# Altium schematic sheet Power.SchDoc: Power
size A4; Date: Not used; ApprovedBy: Not used; CheckedBy: Not used; Author: Not used; CompanyName: STMicroelectronics; DrawnBy: Not used; Engineer: Not used; Organization: Not used; Address1: Not used; Address2: Not used; Address3: Not used; Address4: Not used; DocumentNumber: Not used; Revision: Not used; SheetNumber: 5; SheetTotal: 7
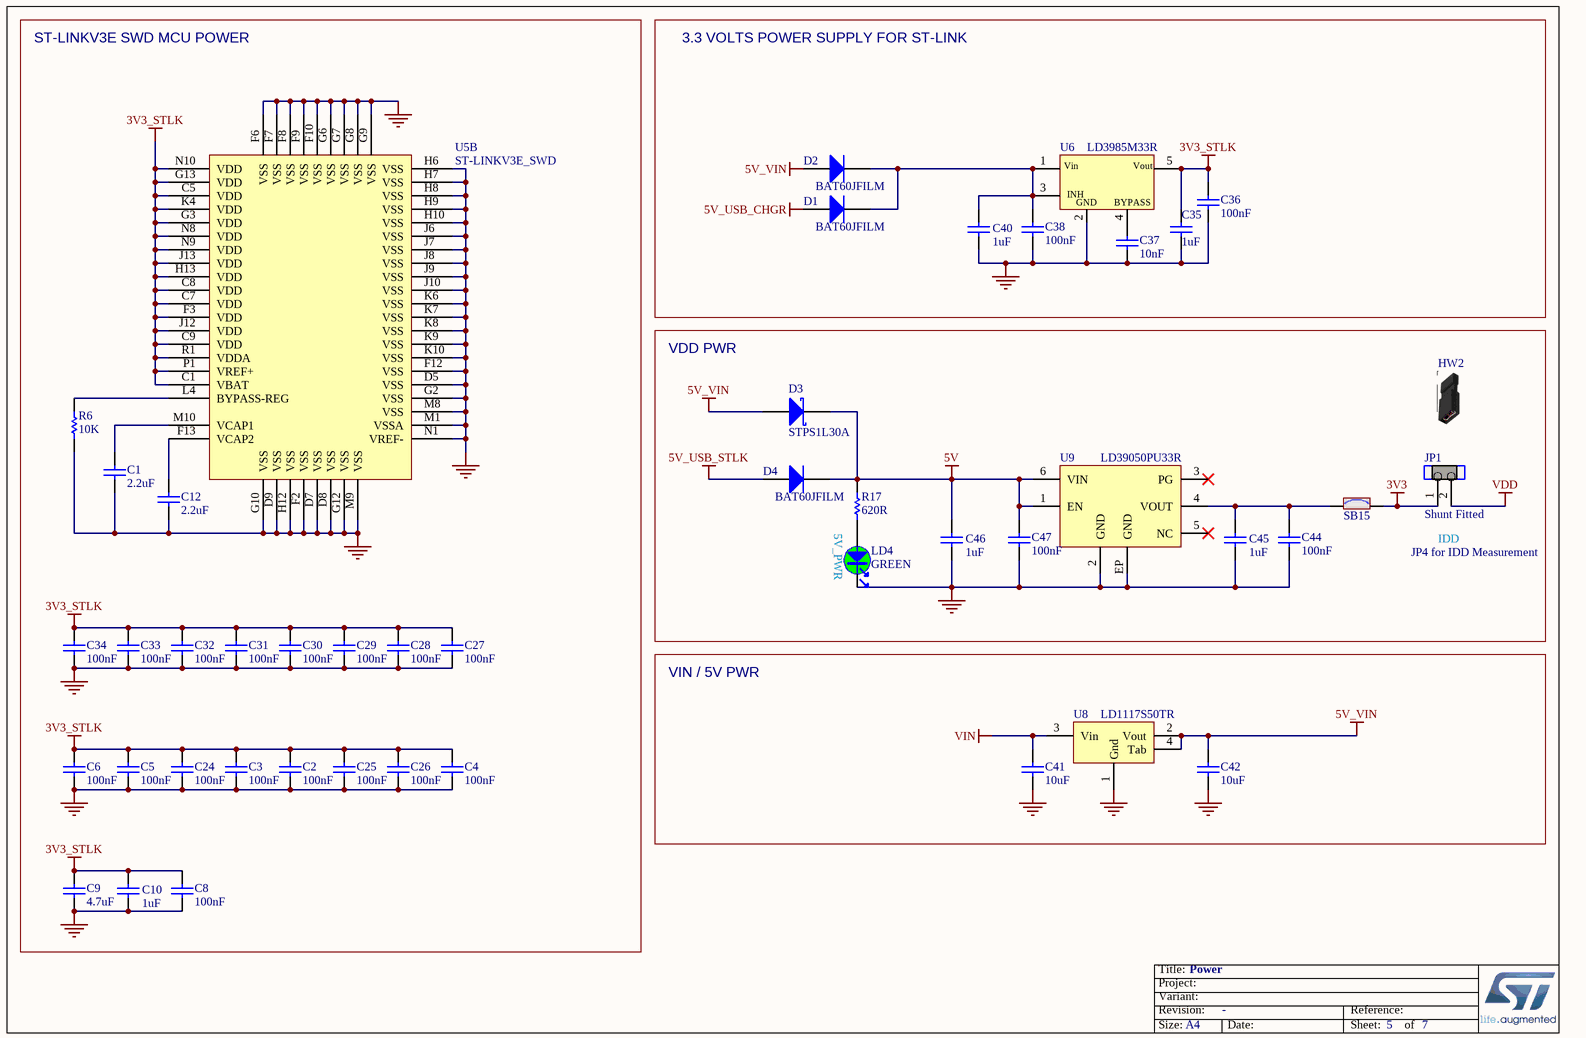
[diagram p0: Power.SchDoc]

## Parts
C1  value 2.2uF  [C0603]
C2  value 100nF  [C0402]
C3  value 100nF  [C0402]
C4  value 100nF  [C0402]
C5  value 100nF  [C0402]
C6  value 100nF  [C0402]
C8  value 100nF  [C0402]
C9  value 4.7uF  [C0603]
C10  value 1uF  [C0603]
C12  value 2.2uF  [C0603]
C24  value 100nF  [C0402]
C25  value 100nF  [C0402]
C26  value 100nF  [C0402]
C27  value 100nF  [C0402]
C28  value 100nF  [C0402]
C29  value 100nF  [C0402]
C30  value 100nF  [C0402]
C31  value 100nF  [C0402]
C32  value 100nF  [C0402]
C33  value 100nF  [C0402]
C34  value 100nF  [C0402]
C35  value 1uF  [C0603]
C36  value 100nF  [C0402]
C37  value 10nF  [C0402]
C38  value 100nF  [C0402]
C40  value 1uF  [C0603]
C41  value 10uF  [C0805]
C42  value 10uF  [C0805]
C44  value 100nF  [C0402]
C45  value 1uF  [C0603]
C46  value 1uF  [C0603]
C47  value 100nF  [C0402]
D1  value BAT60JFILM  [DIO_SOD323]
D2  value BAT60JFILM  [DIO_SOD323]
D3  value STPS1L30A  [DIO_SMA_1A_2K]
D4  value BAT60JFILM  [DIO_SOD323]
HW2  (no value)  (mechanical)
JP1  value Shunt Fitted  [CON_WP_707-2-02-2-20-00]
LD4  value GREEN  [LED_0603_GREEN]
R6  value 10K  [R0402]
R17  value 620R  [R0402]
SB15  (no value)  [SOLDER-BRIDGE_R0603-0R]
U5  value ST-LINKV3E_SWD  [ICC_UFBGA201_176+25_10X10_P065]  (part B of 2)
U6  value LD3985M33R  [REG_SOT23-5L]
U8  value LD1117S50TR  [REG_SOT223-TAB]
U9  value LD39050PU33R  [ICC_DFN6-EPAD_3X3_P095]

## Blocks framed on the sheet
ST-LINKV3E SWD MCU POWER: C1-C6 C8-C10 C12 C24-C34 R6 U5
3.3 VOLTS POWER SUPPLY FOR ST-LINK: C35-C38 C40 D1 D2 U6
VDD PWR: C44-C47 D3 D4 HW2 JP1 LD4 R17 SB15 U9
VIN / 5V PWR: C41 C42 U8

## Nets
3V3: JP1.1 SB15.2
3V3_STLK: C2.2 C3.2 C4.2 C5.2 C6.2 C8.2 C9.2 C10.2 C24.2 C25.2 C26.2 C27.2 C28.2 C29.2 C30.2 C31.2 C32.2 C33.2 C34.2 C35.2 C36.2 U5.C1(VBAT) U5.C5(VDD) U5.C7(VDD) U5.C8(VDD) U5.C9(VDD) U5.F3(VDD) U5.G3(VDD) U5.G13(VDD) U5.H13(VDD) U5.J12(VDD) U5.J13(VDD) U5.K4(VDD) U5.N8(VDD) U5.N9(VDD) U5.N10(VDD) U5.P1(VREF+) U5.R1(VDDA) U6.5(Vout)
5V: C46.2 C47.2 D3.2(K) D4.2(K) R17.2 U9.1(EN) U9.6(VIN)
5V_USB_CHGR: D1.1(A)
5V_USB_STLK: D4.1(A)
5V_VIN: C42.2 D2.1(A) D3.1(A) U8.2(Vout) U8.4(Tab)
GND: C1.1 C2.1 C3.1 C4.1 C5.1 C6.1 C8.1 C9.1 C10.1 C12.1 C24.1 C25.1 C26.1 C27.1 C28.1 C29.1 C30.1 C31.1 C32.1 C33.1 C34.1 C35.1 C36.1 C37.1 C38.1 C40.1 C41.1 C42.1 C44.1 C45.1 C46.1 C47.1 LD4.2 R6.1 U5.D5(VSS) U5.D7(VSS) U5.D8(VSS) U5.D9(VSS) U5.F2(VSS) U5.F6(VSS) U5.F7(VSS) U5.F8(VSS) U5.F9(VSS) U5.F10(VSS) U5.F12(VSS) U5.G2(VSS) U5.G6(VSS) U5.G7(VSS) U5.G8(VSS) U5.G9(VSS) U5.G10(VSS) U5.G12(VSS) U5.H6(VSS) U5.H7(VSS) U5.H8(VSS) U5.H9(VSS) U5.H10(VSS) U5.H12(VSS) U5.J6(VSS) U5.J7(VSS) U5.J8(VSS) U5.J9(VSS) U5.J10(VSS) U5.K6(VSS) U5.K7(VSS) U5.K8(VSS) U5.K9(VSS) U5.K10(VSS) U5.M1(VSSA) U5.M8(VSS) U5.M9(VSS) U5.N1(VREF-) U6.2(GND) U8.1(Gnd) U9.2(GND) U9.EP(GND)
VDD: JP1.2
VIN: C41.2 U8.3(Vin)
NetC1_2: C1.2 U5.M10(VCAP1)
NetC12_2: C12.2 U5.F13(VCAP2)
NetC37_2: C37.2 U6.4(BYPASS)
NetC38_2: C38.2 C40.2 D1.2(K) D2.2(K) U6.1(Vin) U6.3(CE)
NetC44_2: C44.2 C45.2 SB15.1 U9.4(VOUT)
NetLD4_1: LD4.1 R17.1
NetR6_2: R6.2 U5.L4(BYPASS-REG)

Not connected (* = marked no-connect by the designer): U9 3(PG)* 5(NC)*

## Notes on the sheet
- 5V_PWR
- JP4 for IDD Measurement
- IDD

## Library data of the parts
C1 C12 = MCD-00012: Capacitor, MLCC, 2.2uF, 10V, X5R, 10%, 0603, T=0,8mm; Manufacturer_Part_Number: CC0603KRX5R6BB225; Manufacturer: YAGEO; Alternate_Manufacturer_Part_Number: C0603C225K8PACTU; Alternate_Manufacturer: KEMET; Provided_By: SUBCO; Initial_Board_Reference: MB1274
C2-C6 C8 C24-C34 C36 C38 C44 C47 = MCD-00102: Capacitor, MLCC, 100nF, 16V, X7R, 10%, 0402, T=0,5mm; Manufacturer_Part_Number: CC0402KRX7R7BB104; Manufacturer: YAGEO; Provided_By: SUBCO; Initial_Board_Reference: MB1262
C9 = MCD-00009: Capacitor, MLCC, 4.7uF, 16V, X5R, 10%, 0603, T=0.8mm; Manufacturer_Part_Number: CC0603KRX5R7BB475; Manufacturer: YAGEO; Provided_By: SUBCO; Initial_Board_Reference: MB1274
C10 C35 C40 C45 C46 = MCD-00010: Capacitor, MLCC, 1uF, 16V, X5R, 10%, 0603, T=0,8mm; Manufacturer_Part_Number: CC0603KRX5R7BB105; Manufacturer: YAGEO; Provided_By: SUBCO; Initial_Board_Reference: MB1274
C37 = MCD-00011: Capacitor, MLCC, 10nF, 16V, X7R, 10%, 0402, T=0.5mm; Manufacturer_Part_Number: CC0402KRX7R7BB103; Manufacturer: YAGEO; Provided_By: SUBCO; Initial_Board_Reference: MB1274
C41 C42 = MCD-00014: Capacitor, MLCC, 10uF, 25V, X5R, 10%, 0805, T=0,85mm; Manufacturer_Part_Number: CC0805KRX5R8BB106; Manufacturer: YAGEO; Provided_By: SUBCO; Initial_Board_Reference: MB1274
D1 D2 D4 = MCD-00034: BAT60JFILM; Manufacturer: STMICROELECTRONICS; Part_Type: Diode; BMS_Part_Number: 9151097; Provided_By: SUBCO with ST control; Initial_Board_Reference: MB1274
D3 = MCD-01059: LOW DROP POWER SCHOTTKY RECTIFIER 1A 30V VF=0.3V; Part_Type: Diode; Manufacturer: STMICROELECTRONICS; Provided_By: SUBCO with ST control; Initial_Board_Reference: MB1378
HW2 = MCD-01409: SHUNT 1.27mm BLACK; Part_Type: Mechanical; Manufacturer: W & P Products; Alternate_Manufacturer_Part_Number: M50-1900005; Alternate_Manufacturer: HARWIN; Value: 266-101-10-00; Provided_By: SUBCO; Initial_Board_Reference: MB1441; Remark: mechanical parts no footprint. alt MCD-01389
JP1 = MCD-01428: Header, 2x1, 1,27mm, Right Angled, Single Row, Height 3.05mm/1.27mm; Part_Type: Connector; Manufacturer_Part_Number: 707-2-02-2-20-00; Manufacturer: W & P Products; Provided_By: SUBCO; Initial_Board_Reference: MB1441
LD4 = MCD-00050: LED, Green, 0603; Part_Type: Display; Manufacturer_Part_Number: 19-213SYGC/S530-E2/TR8; Manufacturer: EVERLIGHT; Provided_By: SUBCO; Initial_Board_Reference: MB1274
R6 = MCD-00053: Resistor,10K,0402,1%,1/16W; Manufacturer_Part_Number: RC0402FR-0710KL; Manufacturer: YAGEO; Provided_By: SUBCO; Initial_Board_Reference: MB1274
R17 = MCD-00499: Resistor,620R,0402,1%,1/16W; Manufacturer_Part_Number: RC0402FR-07620RL; Manufacturer: YAGEO; Provided_By: SUBCO; Initial_Board_Reference: MBxxxx
SB15 = MCD-00071: Solder Bridge ON; Part_Type: Mechanical; Manufacturer_Part_Number: RC0603JR-070RL; Manufacturer: YAGEO; Provided_By: SUBCO; Initial_Board_Reference: MB1274
U5 = MCD-00596: STM32F723IEK  (STM32F7) BGA176; Part_Type: IC; Manufacturer_Part_Number: STM32F723IEK6; Manufacturer: STMICROELECTRONICS; BMS_Part_Number: 9175300; Provided_By: SUBCO with ST control; Initial_Board_Reference: MB1331
U6 = MCD-00086: Ultra low drop-low noise BiCMOS voltage, regulators low ESR capacitors compatible; Manufacturer: STMICROELECTRONICS; Part_Type: IC; BMS_Part_Number: 9176161; Provided_By: SUBCO with ST control; Initial_Board_Reference: MB1274
U8 = MCD-00088: IC REG LDO 5V 0.8A SOT223; Manufacturer: STMICROELECTRONICS; BMS_Part_Number: 9176133; Provided_By: SUBCO with ST control; Initial_Board_Reference: MB1274
U9 = MCD-00215: Low quiescent current and low noise voltage regulators; Manufacturer: STMICROELECTRONICS; Part_Type: IC; Provided_By: SUBCO with ST control; Initial_Board_Reference: MB1319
